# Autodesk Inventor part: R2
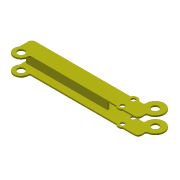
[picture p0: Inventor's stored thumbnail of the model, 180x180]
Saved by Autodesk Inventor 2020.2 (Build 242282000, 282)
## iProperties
Created: 2005-10
Part Number: R2
Document SubType Name: Modeling
Designer: F.Stasiak
Density: 1 g/cm^3
Material: Ogólny
Appearance: Żółta
Manager: www.cadconsulting.pl
Company: Fabian Stasiak CAD Consulting
Author: F.Stasiak
Subject: Zbiór ćwiczeń. Autodesk Inventor 2020. Kurs podstawowy
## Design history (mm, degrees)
sketch "Szkic1"
  geometry: L1 (-467.927, 681.983)-(-2167.927, 681.983); L2 (-2167.927, 891.983)-(-467.927, 891.983); L3 (-2167.927, 681.983)-(-2167.927, 891.983); L4 (-467.927, 681.983)-(-467.927, 891.983)
  constraints: 8 end point, 2 parallel, 1 perpendicular
  dimensions: "d0" = 1700 distance of L1.start L1.end; "d20" = 210 distance of L1.end L2.start
extrude "Wyciągnięcie proste1" new body sketch "Szkic1" stored distance "d4" = 200; taper "d5" = 0 deg
feature "Skorupa1" dims "d6" = 20
sketch "Szkic2"
  geometry: L1 (2167.927, 681.983)-(467.927, 681.983) reference; L2 (2167.927, 891.983)-(2167.927, 681.983) reference; C1 r 100 at (2087.927, 661.983)
  constraints: 1 centre point
  dimensions: "d7" = 20 distance from line of L1 C1.centre; "d8" = 200 diameter of C1; "d9" = 80 distance from line of L2 C1.centre
extrude "Wyciągnięcie proste2" join sketch "Szkic2" distance "d10" = 20; taper "d11" = 0 deg
sketch "Szkic3"
  geometry: C1 r 50 at (726.579, 721.983) reference; C2 r 60 at (726.579, 721.983)
  constraints: 1 centre point
  dimensions: "d12" = 10 radial gap between concentric circles of C2 C1
extrude "Wyciągnięcie proste3" join sketch "Szkic3" distance "d13" = 20; taper "d14" = 0 deg
sketch "Szkic4"
  geometry: L1 (467.927, 891.983)-(2167.927, 891.983) reference; L2 (467.927, 681.983)-(467.927, 891.983) reference; L3 (467.927, 921.983)-(467.927, 891.983); C1 r 125 at (467.927, 921.983)
  constraints: 2 end point, 1 centre point, 1 collinear
  dimensions: "d21" = 250 diameter of C1; "d22" = 30 distance of L3.start L1.start
extrude "Wyciągnięcie proste4" join sketch "Szkic4" distance "d15" = 20; taper "d16" = 0 deg
sketch "Szkic6"
  geometry: C1 r 50 at (726.058, 871.983) reference; C2 r 60 at (726.058, 871.983); A1 r 60 centre (726.579, 721.983) between (681.858, 681.983) and (771.301, 681.983) reference
  constraints: 1 centre point, 1 coincident
  dimensions: "d23" = 10 radial gap between concentric circles of C2 C1
extrude "Wyciągnięcie proste6" join sketch "Szkic6" distance "d24" = 20; taper "d25" = 0 deg
sketch "Szkic7"
  geometry: L1 (0, 0)-(1700, 0) reference; L2 (530, -85)-(1670, -85); L3 (1670, -85)-(1670, -110); L4 (1670, -110)-(530, -110); L5 (530, -110)-(530, -85); L6 (1700, 0)-(1700, -170) reference
  constraints: 8 end point, 2 parallel, 1 horizontal, 1 perpendicular
  dimensions: "d26" = 1140 distance of L3.end L4.end; "d27" = 25 distance of L2.end L3.end; "d28" = 85 distance between parallel lines of L1 L2; "d29" = 30 distance between parallel lines of L6 L3
extrude "Wyciągnięcie proste7" join sketch "Szkic7" stored distance "d30" = 20; taper "d31" = 0 deg
fillet "Zaokrąglenie1" dims "d32" = 20, "d33" = 50
mirror "Lustro1"
sketch "Szkic8"
  geometry: A1 r 60 centre (726.058, 871.983) between (782.627, 891.983) and (669.49, 891.983) reference; A2 r 60 centre (726.579, 721.983) between (681.858, 681.983) and (771.301, 681.983) reference
hole "Otwór1" sketch "Szkic8" at (726.058, 871.983), (726.579, 721.983) diameter "d34" = 60; stored, may be unused: countersink angle "d38" = 90 deg, drill point angle "d40" = 118 deg; dims "d35" = 6, "d36" = 4, "d37" = 2, "d39" = 8
sketch "Szkic9"
  geometry: A1 r 125 centre (467.927, 921.983) between (450.686, 1045.788) and (592.927, 921.983) reference; A2 r 100 centre (2087.927, 661.983) between (1987.927, 661.983) and (2171.261, 717.26) reference
hole "Otwór2" sketch "Szkic9" at (2087.927, 661.983), (467.927, 921.983) diameter "d41" = 100; stored, may be unused: countersink angle "d45" = 90 deg, drill point angle "d47" = 118 deg; dims "d42" = 6, "d43" = 4, "d44" = 2, "d46" = 8
node "Bryła1"
node "Korpusy bryłowe"
node "Korpusy powierzchniowe"
node "Odniesienie1"
node "Odniesienie3"
node "Odniesienie4"
